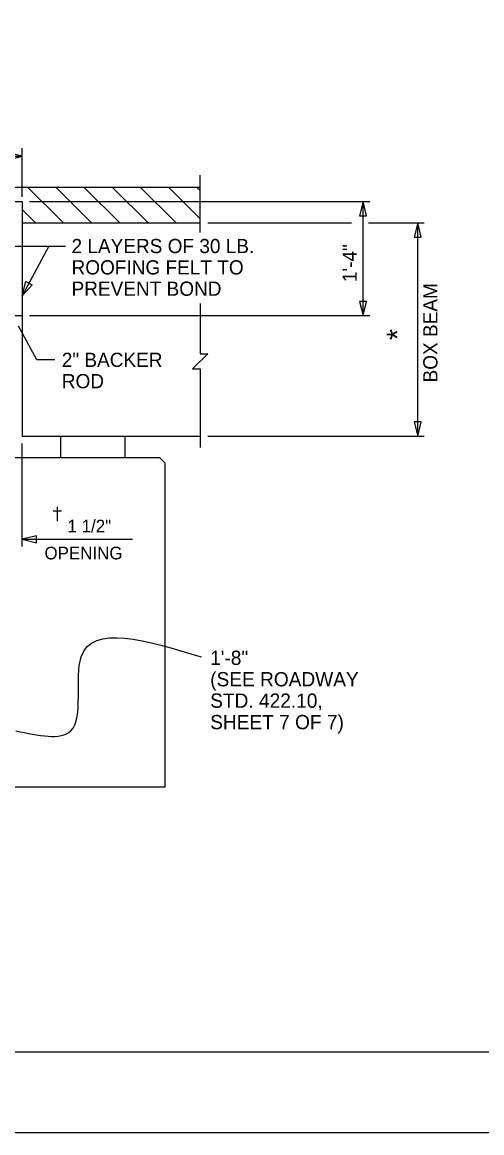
# Model space of a CAD drawing. Extents: x -151 to 116, y -17 to 117.
# Drawn here: x 50.16 to 62.29, y 0 to 29.29 of the extents above; entities that cross this region are included whole.
import ezdxf

# ---------------------------------------------------------------- set-up
doc = ezdxf.new("R2010")
doc.units = 0
for name, color, linetype in [('Arrowhead Terminators', 7, 'Continuous'), ('Arrowhead Terminators CELL', 7, 'Continuous'), ('Dimension Lines', 7, 'Continuous'), ('Mis Object Lines', 7, 'Continuous'), ('Plan Sheet', 7, 'Continuous'), ('Plot Shape', 7, 'Continuous'), ('Text', 7, 'Continuous'), ('User Information Notes', 7, 'Continuous')]:
    doc.layers.add(name, color=color, linetype=linetype)

msp = doc.modelspace()

# ---------------------------------------------------------------- linework, layer by layer
at = {"layer": 'Arrowhead Terminators'}
for points in [[(50.163, 25.756), (49.788, 25.85), (49.788, 25.662)], [(50.163, 15.655), (50.538, 15.562), (50.538, 15.749)]]:
    msp.add_lwpolyline(points, close=True, dxfattribs=at)
at = {"layer": 'Arrowhead Terminators CELL'}
for points in [[(59.156, 24.561), (59.062, 24.186), (59.249, 24.186)], [(60.595, 23.999), (60.502, 23.624), (60.689, 23.624)], [(50.163, 22.077), (50.258, 22.452), (50.423, 22.364)], [(59.156, 21.555), (59.249, 21.93), (59.062, 21.93)], [(60.595, 18.374), (60.689, 18.749), (60.502, 18.749)]]:
    msp.add_lwpolyline(points, close=True, dxfattribs=at)
at = {"layer": 'Dimension Lines'}
for p, q in [((50.163, 24.683), (50.163, 25.97)), ((47.72, 25.756), (50.163, 25.756)), ((50.352, 24.561), (59.332, 24.561)), ((59.156, 21.555), (59.156, 24.561)), ((55.056, 23.999), (58.852, 23.999)), ((59.301, 23.999), (60.768, 23.999)), ((60.595, 18.374), (60.595, 23.999)), ((50.865, 23.389), (50.163, 22.077)), ((50.352, 21.555), (59.332, 21.555)), ((50.163, 15.464), (50.163, 18.18)), ((55.056, 18.374), (60.768, 18.374)), ((50.163, 15.655), (53.069, 15.655))]:
    msp.add_line(p, q, dxfattribs=at)
for points in [[(48.52, 21.555), (49.017, 23.389), (51.302, 23.389)], [(51.021, 20.388), (50.548, 20.388), (50.068, 21.278)]]:
    msp.add_lwpolyline(points, dxfattribs=at)
at = {"layer": 'Mis Object Lines'}
for p, q in [((54.857, 23.742), (54.857, 25.26)), ((54.857, 24.937), (35.131, 24.937)), ((50.312, 24.937), (51.25, 23.999)), ((51.055, 24.937), (51.994, 23.999)), ((51.799, 24.937), (52.738, 23.999)), ((52.543, 24.937), (53.481, 23.999)), ((53.286, 24.937), (54.225, 23.999)), ((54.03, 24.937), (54.857, 24.11)), ((54.773, 24.937), (54.857, 24.854)), ((35.131, 24.561), (50.163, 24.561)), ((50.163, 24.561), (50.163, 18.374)), ((50.163, 24.351), (50.516, 23.999)), ((50.163, 23.999), (54.857, 23.999)), ((54.856, 21.877), (54.856, 20.549)), ((47.72, 21.555), (50.163, 21.555)), ((54.856, 20.15), (54.856, 18.072)), ((50.163, 18.374), (54.856, 18.374)), ((51.175, 18.373), (51.175, 17.809)), ((52.867, 18.373), (52.867, 17.809)), ((49.976, 17.81), (53.782, 17.81)), ((53.782, 17.81), (53.923, 17.669)), ((53.923, 17.669), (53.923, 9.114)), ((53.923, 9.114), (47.72, 9.114))]:
    msp.add_line(p, q, dxfattribs=at)
msp.add_lwpolyline([(54.857, 20.549), (55.056, 20.549), (54.657, 20.15), (54.856, 20.15)], dxfattribs=at)
at = {"layer": 'Plan Sheet'}
msp.add_line((3.71, 2.134), (116.351, 2.134), dxfattribs=at)
at = {"layer": 'Plot Shape'}
msp.add_lwpolyline([(0, 77.44), (116.382, 77.44), (116.382, 0), (0, 0)], close=True, dxfattribs=at)
at = {"layer": 'Text'}
for p, q in [((51.089, 16.132), (51.089, 16.507)), ((50.977, 16.403), (51.201, 16.403))]:
    msp.add_line(p, q, dxfattribs=at)
at = {"layer": 'User Information Notes'}
msp.add_spline([(49.994, 10.603), (51.443, 10.603), (51.716, 12.552), (54.881, 12.552)], degree=3, dxfattribs=at)

# ---------------------------------------------------------------- texts
at = {"layer": 'Text'}
for s, height, p in [('2 LAYERS OF 30 LB.', 0.375, (51.463, 23.202)), ('ROOFING FELT TO', 0.375, (51.463, 22.639)), ('PREVENT BOND', 0.375, (51.463, 22.077)), ('2" BACKER', 0.3747, (51.207, 20.2)), ('ROD', 0.3747, (51.207, 19.638)), ('1 1/2"', 0.3339, (51.357, 15.835)), ('OPENING', 0.3339, (50.749, 15.124))]:
    msp.add_text(s, height=height, dxfattribs=at).set_placement(p)
for s, p in [('1\'-4"', (58.988, 22.438)), ('BOX BEAM', (61.117, 19.791))]:
    msp.add_text(s, height=0.375, rotation=90, dxfattribs=at).set_placement(p)
at = {"layer": 'User Information Notes'}
msp.add_text('*', height=0.562, rotation=90, dxfattribs=at).set_placement((60.341, 20.91))
for s, height, p in [('1\'-8"', 0.3766, (55.121, 12.34)), ('(SEE ROADWAY', 0.37663, (55.121, 11.775)), ('STD. 422.10,', 0.37663, (55.121, 11.21)), ('SHEET 7 OF 7)', 0.37663, (55.121, 10.645))]:
    msp.add_text(s, height=height, dxfattribs=at).set_placement(p)

doc.saveas('drawing.dxf')
